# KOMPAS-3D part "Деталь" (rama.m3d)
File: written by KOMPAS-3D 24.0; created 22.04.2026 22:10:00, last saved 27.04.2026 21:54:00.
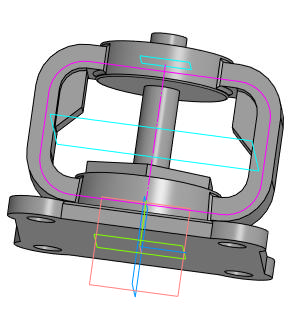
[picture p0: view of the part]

Document properties: Автор: mrdid; Полное имя файла: C:\Работа\ГОТОВЫЕ ИСХОДНИКИ\VSO2130M-F-S Клапан запорный сальниковый DN.ru Ду15-100 Ру40\исходные материалы\DN80\rama.m3d

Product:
- Part/product: Деталь
    Масса: 4.634846

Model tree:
1. Эскиз:2
2. Элемент выдавливания:1
     Расстояние 1 = 10
3. Эскиз:3  (with: Грань.Элемент выдавливания:1, Ребро.Элемент выдавливания:1)
4. Элемент выдавливания:2
     Расстояние 2 = 10
5. Массив по сетке:1  (with: Элемент выдавливания:2, Эскиз:3)  (4 pattern instances)
     Угол раствора = 90
6. Эскиз:4  (with: Грань.Элемент выдавливания:1)
7. Элемент выдавливания:3
     Угол 1 = -3
8. Эскиз:5  (with: Грань.Элемент выдавливания:3, Ребро.Элемент выдавливания:3)
9. Элемент выдавливания:4
10. Эскиз:23  (with: Грань.Элемент выдавливания:4, Ребро.Элемент выдавливания:4)
11. Элемент выдавливания:21  (labels: Деталь2; Грань.Твердое тело1)
     Расстояние 1 = 78.7225
12. Эскиз:7  (with: Грань.Элемент выдавливания:4, Ребро.Элемент выдавливания:3)
13. Элемент выдавливания:6  (with: Грань.Элемент выдавливания:3)
     Расстояние 2 = 7
14. Смещенная плоскость:4  (labels: Деталь2; Грань.Твердое тело1)
     Расстояние = 15
15. Эскиз:24  (with: Ребро.Элемент выдавливания:3)
16. Элемент выдавливания:22
     Расстояние 1 = 5; Расстояние 2 = 15
17. Эскиз:25  (with: Ребро.Элемент выдавливания:3)
18. Эскиз:26  (with: Ребро.Элемент выдавливания:3)
19. Элемент по траектории:1
     Длина траектории = 367.109
20. Скругление:8  (with: Ребро.Элемент по траектории:1)
     Радиус = 2
21. Скругление:9  (with: Ребро.Элемент по траектории:1)
     Радиус = 2
22. Смещенная плоскость:5  (with: Грань.Элемент выдавливания:1)
23. Эскиз:27  (with: Вершина.Элемент по траектории:1)
24. Элемент выдавливания:23  (with: Грань.Элемент выдавливания:22)
     Расстояние 1 = 35.4725; Смещение 1 = 5
25. Скругление:1  (with: Ребро.Элемент выдавливания:1)
     Радиус = 1.5
26. Скругление:10  (with: Ребро.Элемент выдавливания:22)
     Радиус = 1
27. Фаска:1  (with: Ребро.Элемент выдавливания:23)
     Угол = 45; Длина 1 = 13; Длина 2 = 13

Expressions: DN/2; DN/4; DN/6; H/4-10; D2/2-15; D2-15*2
Referenced files in C:\Работа\ГОТОВЫЕ ИСХОДНИКИ\VSO2130M-F-S Клапан запорный сальниковый DN.ru Ду15-100 Ру40\исходные материалы\DN80\: VSO2130M-F-S Клапан запорный DN.ru Ду80 Ру40.a3d
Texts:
  DN+5
  nd+20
